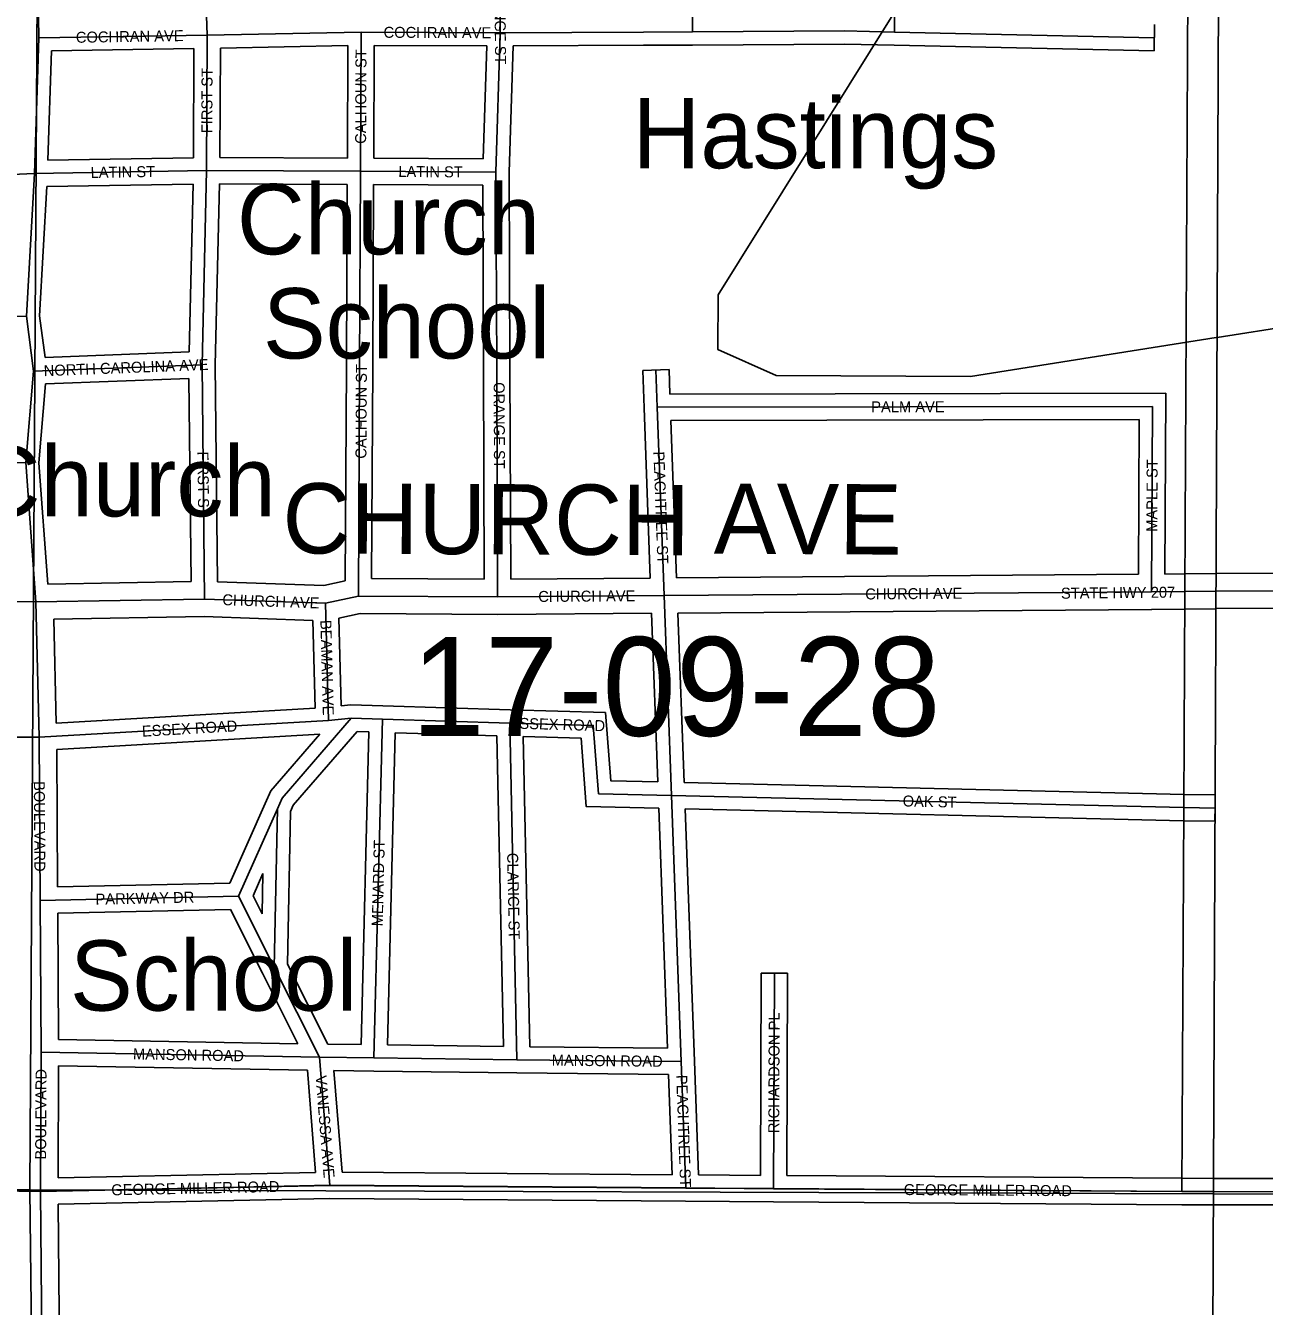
# Model space of a CAD drawing. Extents: x 418523 to 616617, y 1878279 to 2196743.
# Drawn here: x 494801 to 497620, y 1954823 to 1957739 of the extents above; entities that cross this region are included whole.
import ezdxf

# ---------------------------------------------------------------- set-up
doc = ezdxf.new("R2010")
doc.units = 0
for name, color, linetype in [('Level 1', 7, 'Continuous'), ('Level 2', 7, 'Continuous'), ('Level 22', 7, 'Continuous'), ('Level 23', 7, 'Continuous'), ('Level 28', 7, 'Continuous'), ('Level 31', 7, 'Continuous'), ('Level 32', 7, 'Continuous'), ('Level 34', 7, 'Continuous'), ('Level 44', 7, 'Continuous'), ('Level 57', 7, 'Continuous'), ('Level 63', 7, 'Continuous'), ('Level 7', 7, 'Continuous'), ('Level 8', 7, 'Continuous')]:
    doc.layers.add(name, color=color, linetype=linetype)

msp = doc.modelspace()

# ---------------------------------------------------------------- linework, layer by layer
at = {"layer": 'Level 1'}
for p, q in [((494842.153, 1960333.163), (494809.94, 1955087.849)), ((494809.94, 1955087.849), (489587.693, 1955086.288)), ((494809.94, 1955087.849), (494874.469, 1949774.808)), ((497503.83, 1955079.028), (494809.94, 1955087.849)), ((500077.56, 1955070.604), (497503.83, 1955079.028))]:
    msp.add_line(p, q, dxfattribs=at)
at = {"layer": 'Level 22'}
for p, q in [((495482.85, 1956423.768), (495557.843, 1956440.169)), ((495874.665, 1956438.423), (495557.843, 1956440.169)), ((495874.665, 1956438.423), (496253.728, 1956441.136)), ((496253.728, 1956441.136), (497362.983, 1956449.785)), ((497362.983, 1956449.785), (497438.86, 1956450.548)), ((494148.895, 1956430.348), (494824.127, 1956427.016)), ((495207.65, 1956433.336), (494824.127, 1956427.016)), ((494831.03, 1956118.601), (494824.127, 1956427.016)), ((495482.85, 1956423.768), (495207.65, 1956433.336)), ((494833.53, 1955746.929), (494831.03, 1956118.601)), ((494835.826, 1955401.441), (494833.53, 1955746.929)), ((494834.44, 1955084.699), (494835.826, 1955401.441))]:
    msp.add_line(p, q, dxfattribs=at)
for points in [[(497509.735, 1956451.334), (498093.802, 1956453.183), (498594.582, 1956559.406), (498750.081, 1956620.198)], [(497438.86, 1956450.548), (497509.658, 1956451.334), (497509.735, 1956451.334)], [(494935.568, 1953600.158), (494845.41, 1953892.572), (494834.44, 1955084.699)]]:
    msp.add_lwpolyline(points, dxfattribs=at)
at = {"layer": 'Level 23'}
for p, q in [((495177.235, 1956472.84), (494851.225, 1956467.468)), ((495479.216, 1956463.919), (495237.245, 1956472.331)), ((495479.216, 1956463.918), (495528.035, 1956474.595)), ((495844.52, 1956478.59), (495588.067, 1956480.003)), ((495904.521, 1956478.637), (496222.261, 1956480.912)), ((496282.286, 1956481.361), (497333.185, 1956489.553)), ((497393.189, 1956490.091), (497438.458, 1956490.546)), ((496285.214, 1956401.38), (497363.295, 1956409.785)), ((497363.386, 1956409.786), (497439.263, 1956410.549)), ((497439.305, 1956410.55), (497509.563, 1956411.33)), ((495207.286, 1956393.321), (494865.02, 1956387.682)), ((494870.318, 1956150.93), (494865.02, 1956387.683)), ((495453.876, 1956384.75), (495207.285, 1956393.321)), ((495513.77, 1956389.583), (495562.058, 1956400.143)), ((495874.952, 1956398.423), (495562.058, 1956400.143)), ((495874.952, 1956398.423), (496225.189, 1956400.93)), ((494873.324, 1955777.82), (494871.219, 1956090.879)), ((494875.634, 1955430.724), (494873.725, 1955717.813)), ((494874.576, 1955115.527), (494875.693, 1955370.711))]:
    msp.add_line(p, q, dxfattribs=at)
for points in [[(497509.907, 1956491.336), (498089.544, 1956493.171), (498583.072, 1956597.856), (498735.516, 1956657.453)], [(497509.563, 1956411.33), (497509.944, 1956411.334), (498098.06, 1956413.196), (498606.091, 1956520.956), (498764.647, 1956582.943)], [(497438.416, 1956490.546), (497509.372, 1956491.334), (497509.907, 1956491.336)], [(494970.103, 1953623.913), (494885.356, 1953898.779), (494874.71, 1955055.516)]]:
    msp.add_lwpolyline(points, dxfattribs=at)
at = {"layer": 'Level 31'}
for p, q in [((495213.895, 1957717.031), (495199.21, 1958134.214)), ((494830.385, 1957710.711), (494823.845, 1958102.402)), ((495880.887, 1957722.481), (495879.955, 1957799.946)), ((496317.39, 1957796.949), (496318.029, 1957724.578)), ((496778.001, 1957794.223), (496778.015, 1957724.036)), ((495213.895, 1957717.031), (495564.075, 1957723.863)), ((495562.694, 1957407.121), (495564.075, 1957723.863)), ((495880.887, 1957722.481), (495564.075, 1957723.863)), ((495870.935, 1957405.413), (495880.887, 1957722.481)), ((495880.887, 1957722.481), (496206.6, 1957723.972)), ((496206.6, 1957723.972), (496318.029, 1957724.578)), ((496318.029, 1957724.578), (496664.379, 1957726.711)), ((496664.379, 1957726.711), (496778.015, 1957724.036)), ((496778.015, 1957724.036), (497369.374, 1957711.296)), ((494820.462, 1957402.37), (494830.385, 1957710.711)), ((495213.895, 1957717.031), (494830.385, 1957710.711)), ((495212.547, 1957408.652), (495213.895, 1957717.031)), ((494145.101, 1957372.246), (494820.462, 1957402.37)), ((494802.214, 1957077.337), (494820.462, 1957402.37)), ((495212.547, 1957408.652), (494820.462, 1957402.37)), ((495202.045, 1956966.85), (495212.547, 1957408.652)), ((495562.694, 1957407.121), (495212.547, 1957408.652)), ((495560.756, 1956962.736), (495562.694, 1957407.121)), ((495870.935, 1957405.413), (495562.694, 1957407.121)), ((495872.802, 1956958.829), (495870.935, 1957405.413)), ((494126.92, 1957063.942), (494802.214, 1957077.337)), ((494818.49, 1956952.167), (494802.214, 1957077.337)), ((494818.49, 1956952.167), (495202.045, 1956966.85)), ((495207.65, 1956433.336), (495202.045, 1956966.85)), ((495557.843, 1956440.169), (495560.756, 1956962.736)), ((494800.752, 1956743.867), (494818.49, 1956952.167)), ((495874.665, 1956438.423), (495872.802, 1956958.829)), ((496235.007, 1956955.07), (496238.13, 1956869.96)), ((496238.13, 1956869.96), (497365.12, 1956871.985)), ((496238.13, 1956869.96), (496253.728, 1956441.136)), ((497365.12, 1956871.985), (497362.983, 1956449.785)), ((494133.744, 1956738.799), (494800.752, 1956743.867)), ((494824.127, 1956427.016), (494800.752, 1956743.867)), ((496253.728, 1956441.136), (496270.484, 1955986.125)), ((495489.94, 1956156.811), (495482.85, 1956423.768)), ((494831.03, 1956118.601), (495489.94, 1956156.811)), ((495541.71, 1956162.039), (495489.94, 1956156.811)), ((495541.71, 1956162.039), (495612.495, 1956159.911)), ((495612.495, 1956159.911), (495593.26, 1955388.308)), ((495612.495, 1956159.911), (495902.621, 1956151.009)), ((495902.621, 1956151.009), (495918.652, 1955384.343)), ((494164.045, 1956121.534), (494831.03, 1956118.601)), ((496270.484, 1955986.125), (497436.423, 1955958.526)), ((496270.484, 1955986.125), (496292.616, 1955380.17)), ((495285.015, 1955756.952), (495373.505, 1955955.851)), ((495373.505, 1955955.851), (495366.532, 1955594.767)), ((497436.423, 1955958.526), (497507.53, 1955957.129)), ((494833.53, 1955746.929), (495285.015, 1955756.952)), ((495285.015, 1955756.952), (495366.532, 1955594.767)), ((495366.532, 1955594.767), (495469.452, 1955389.94)), ((496502.8, 1955090.874), (496504.609, 1955581.444)), ((495469.452, 1955389.94), (494835.826, 1955401.441)), ((495492.943, 1955098.181), (495469.452, 1955389.94)), ((495469.452, 1955389.94), (495593.26, 1955388.308)), ((495593.26, 1955388.308), (495918.652, 1955384.343)), ((495918.652, 1955384.343), (496292.616, 1955380.17)), ((496292.616, 1955380.17), (496302.796, 1955092.107)), ((494834.44, 1955084.699), (495492.943, 1955098.181)), ((496302.796, 1955092.107), (495492.943, 1955098.181)), ((496502.8, 1955090.874), (496302.796, 1955092.107)), ((497432.022, 1955084.306), (496502.8, 1955090.874)), ((498740.975, 1955083.411), (497503.851, 1955083.997))]:
    msp.add_line(p, q, dxfattribs=at)
for points in [[(495373.505, 1955955.851), (495384.088, 1955980.171), (495541.71, 1956162.039)], [(495902.621, 1956151.009), (496092.442, 1956145.455), (496104.465, 1955990.12), (496270.484, 1955986.125)], [(493517.187, 1955074.501), (493992.548, 1955097.13), (494834.44, 1955084.699)], [(497503.851, 1955083.997), (497503.77, 1955083.997), (497432.022, 1955084.306)]]:
    msp.add_lwpolyline(points, dxfattribs=at)
at = {"layer": 'Level 32'}
for p, q in [((497370.02, 1957741.288), (497368.729, 1957681.301)), ((495243.767, 1957687.606), (495533.941, 1957693.268)), ((495532.825, 1957437.251), (495533.942, 1957693.268)), ((495592.825, 1957436.955), (495593.945, 1957693.731)), ((495849.935, 1957692.615), (495593.945, 1957693.731)), ((495841.868, 1957435.575), (495849.935, 1957692.615)), ((495900.94, 1957405.003), (495909.966, 1957692.612)), ((495909.966, 1957692.612), (496206.739, 1957693.971)), ((496206.765, 1957693.971), (496318.193, 1957694.578)), ((496318.215, 1957694.578), (496664.12, 1957696.706)), ((496664.12, 1957696.706), (496777.31, 1957694.043)), ((496777.37, 1957694.042), (497368.729, 1957681.301)), ((494851.46, 1957432.87), (494859.451, 1957681.184)), ((495183.761, 1957686.528), (494859.451, 1957681.184)), ((495182.676, 1957438.176), (495183.761, 1957686.528)), ((495242.679, 1957438.521), (495243.767, 1957687.607)), ((495182.676, 1957438.177), (494851.46, 1957432.87)), ((495532.825, 1957437.251), (495242.679, 1957438.521)), ((495841.868, 1957435.574), (495592.825, 1957436.955)), ((495902.802, 1956958.954), (495900.939, 1957405.003)), ((494832.324, 1957078.439), (494848.852, 1957372.82)), ((495181.814, 1957378.154), (494848.852, 1957372.82)), ((495172.725, 1956995.75), (495181.815, 1957378.154)), ((495232.05, 1956966.65), (495241.84, 1957378.521)), ((495532.564, 1957377.251), (495241.84, 1957378.522)), ((495530.757, 1956962.867), (495532.564, 1957377.251)), ((495590.757, 1956962.605), (495592.564, 1957376.954)), ((495841.06, 1957375.576), (495592.564, 1957376.953)), ((495842.802, 1956958.704), (495841.06, 1957375.576)), ((494844.71, 1956983.192), (494832.324, 1957078.439)), ((494844.71, 1956983.192), (495172.725, 1956995.75)), ((495237.245, 1956472.331), (495232.051, 1956966.651)), ((495528.035, 1956474.595), (495530.757, 1956962.904)), ((495588.067, 1956480.003), (495590.757, 1956962.568)), ((494846.134, 1956923.201), (495172.371, 1956935.691)), ((495177.234, 1956472.84), (495172.371, 1956935.691)), ((495844.52, 1956478.59), (495842.802, 1956958.721)), ((495904.521, 1956478.638), (495902.802, 1956958.936)), ((496264.988, 1956956.17), (496205.027, 1956953.97)), ((496205.027, 1956953.97), (496208.15, 1956868.859)), ((496264.988, 1956956.17), (496267.049, 1956900.011)), ((494830.848, 1956743.696), (494846.134, 1956923.201)), ((496267.049, 1956900.011), (497395.275, 1956902.039)), ((497395.275, 1956902.04), (497393.189, 1956490.091)), ((496208.149, 1956868.869), (496222.262, 1956480.913)), ((496269.24, 1956840.014), (497334.969, 1956841.93)), ((496269.24, 1956840.013), (496282.286, 1956481.361)), ((497334.969, 1956841.929), (497333.185, 1956489.553)), ((494851.226, 1956467.468), (494830.848, 1956743.696)), ((495459.179, 1956185.076), (495453.876, 1956384.75)), ((495519.073, 1956189.906), (495513.77, 1956389.583)), ((496225.188, 1956400.93), (496239.331, 1956016.882)), ((496285.214, 1956401.38), (496299.425, 1956015.448)), ((494870.318, 1956150.93), (495459.179, 1956185.076)), ((495540.65, 1956192.083), (495519.073, 1956189.905)), ((495540.65, 1956192.083), (495613.396, 1956189.897)), ((495613.415, 1956189.897), (495903.541, 1956180.996)), ((494871.219, 1956090.881), (495470.455, 1956125.629)), ((495555.05, 1956131.623), (495581.761, 1956130.82)), ((495581.761, 1956130.819), (495564.009, 1955418.696)), ((495641.735, 1956128.998), (495624.009, 1955417.936)), ((495641.735, 1956128.998), (495873.224, 1956121.895)), ((495873.224, 1956121.896), (495888.01, 1955414.72)), ((495933.275, 1956120.097), (495948.04, 1955414.017)), ((496299.425, 1956015.447), (497437.133, 1955988.518)), ((497437.012, 1955988.521), (497507.738, 1955987.131)), ((497508.12, 1955987.124), (497507.63, 1955962.251)), ((497507.738, 1955987.131), (497508.12, 1955987.124)), ((495265.336, 1955786.523), (495346.095, 1955968.046)), ((495403.386, 1955949.329), (495396.671, 1955601.606)), ((496241.535, 1955956.811), (496261.488, 1955410.519)), ((496301.628, 1955955.377), (497435.713, 1955928.534)), ((496301.628, 1955955.377), (496322.598, 1955381.265)), ((497507.63, 1955962.209), (497506.941, 1955927.133)), ((497507.63, 1955962.251), (497507.63, 1955962.245)), ((497507.63, 1955962.245), (497507.63, 1955962.242)), ((497507.63, 1955962.242), (497507.63, 1955962.241)), ((497507.63, 1955962.241), (497507.63, 1955962.239)), ((497507.63, 1955962.239), (497507.63, 1955962.227)), ((497507.63, 1955962.227), (497507.63, 1955962.209)), ((497435.834, 1955928.531), (497506.941, 1955927.133)), ((495318.2, 1955757.732), (495340.648, 1955808.19)), ((495340.648, 1955808.19), (495338.879, 1955716.59)), ((494873.325, 1955777.821), (495265.337, 1955786.523)), ((495318.2, 1955757.733), (495338.879, 1955716.591)), ((494873.725, 1955717.812), (495266.726, 1955726.537)), ((495266.727, 1955726.537), (495339.728, 1955581.294)), ((495396.67, 1955601.605), (495488.075, 1955419.696)), ((495339.726, 1955581.297), (495420.353, 1955420.836)), ((496472.912, 1955121.059), (496474.609, 1955581.554)), ((496474.609, 1955581.554), (496534.609, 1955581.332)), ((496532.911, 1955120.663), (496534.609, 1955581.332)), ((495420.353, 1955420.836), (494875.634, 1955430.724)), ((495488.075, 1955419.696), (495564.008, 1955418.696)), ((495624.01, 1955417.936), (495888.01, 1955414.719)), ((495948.04, 1955414.017), (496261.489, 1955410.519)), ((495441.731, 1955360.436), (494875.694, 1955370.711)), ((495460.484, 1955127.523), (495441.731, 1955360.436)), ((495520.642, 1955127.974), (495502, 1955359.507)), ((495502, 1955359.507), (495592.865, 1955358.31)), ((495592.895, 1955358.309), (495918.286, 1955354.345)), ((496322.599, 1955381.229), (496331.762, 1955121.929)), ((495918.317, 1955354.345), (496263.646, 1955350.49)), ((496263.647, 1955350.49), (496271.71, 1955122.341)), ((494874.576, 1955115.527), (495460.483, 1955127.523)), ((496271.71, 1955122.341), (495520.643, 1955127.974)), ((496472.912, 1955121.059), (496331.763, 1955121.929)), ((497432.234, 1955114.306), (496532.911, 1955120.663)), ((498740.99, 1955113.411), (497503.98, 1955113.998)), ((494874.711, 1955055.516), (495493.138, 1955068.177)), ((496302.572, 1955062.107), (495493.138, 1955068.178)), ((496502.616, 1955060.873), (496302.612, 1955062.106)), ((497431.81, 1955054.306), (496502.59, 1955060.873)), ((498740.961, 1955053.411), (497503.722, 1955053.996))]:
    msp.add_line(p, q, dxfattribs=at)
for points in [[(495903.498, 1956180.997), (496120.272, 1956174.654), (496132.285, 1956019.46), (496239.331, 1956016.882)], [(495346.095, 1955968.046), (495358.41, 1955996.351), (495470.455, 1956125.629)], [(495403.385, 1955949.329), (495409.765, 1955963.99), (495555.05, 1956131.622)], [(495933.275, 1956120.098), (496064.612, 1956116.256), (496076.647, 1955960.779), (496241.535, 1955956.811)], [(497503.98, 1955113.998), (497503.841, 1955113.998), (497432.151, 1955114.307)], [(497503.722, 1955053.996), (497503.698, 1955053.996), (497431.892, 1955054.306)]]:
    msp.add_lwpolyline(points, dxfattribs=at)
at = {"layer": 'Level 63'}
for points in [[(457652.636, 1924182.684), (497370.053, 1923990.389), (497565.655, 1969446.889), (457897.306, 1969639.697), (457652.636, 1924182.684)], [(497370.053, 1923990.389), (537087.279, 1923840.983), (537233.896, 1969297.112), (497565.655, 1969446.889), (497370.053, 1923990.389)]]:
    msp.add_lwpolyline(points, dxfattribs=at)
at = {"layer": 'Level 7'}
for p, q in [((497512.22, 1957028.746), (498746.857, 1957223.191)), ((497509.962, 1957028.391), (497512.22, 1957028.746))]:
    msp.add_line(p, q, dxfattribs=at)
msp.add_lwpolyline([(497509.962, 1957028.391), (496950.935, 1956939.702), (496509.117, 1956942.067), (496376.064, 1957001.136), (496376.711, 1957126.18), (496822.365, 1957840.721), (496998.544, 1958048.178), (497258.204, 1958280.216), (497384.103, 1958437.951), (497426.471, 1958562.775), (497445.533, 1959012.836), (497521.83, 1959262.276)], dxfattribs=at)
at = {"layer": 'Level 8'}
msp.add_lwpolyline([(493498.576, 1959054.451), (493702.58, 1959049.453), (493808.581, 1959050.455), (494828.599, 1959053.466), (495470.61, 1959016.473), (496061.62, 1959013.48), (496359.625, 1959000.482), (496501.628, 1958994.484), (496771.632, 1958984.486), (496828.633, 1959009.488), (497004.635, 1959034.491), (497375.641, 1959032.495), (497451.643, 1959031.496), (497438.692, 1956450.436), (497436.701, 1955958.425), (497431.718, 1955084.405), (496502.702, 1955090.394), (496302.699, 1955092.392), (495492.685, 1955098.383), (494834.675, 1955084.375), (493992.66, 1955097.366), (493517.653, 1955074.36), (492703.64, 1955079.351)], dxfattribs=at)

# ---------------------------------------------------------------- texts
at = {"layer": 'Level 2'}
msp.add_text('17-09-28', height=225, dxfattribs=at).set_placement((495678.508, 1956121.747))
at = {"layer": 'Level 28'}
for s, p in [('CHURCH', (495384.98, 1956537.411)), ('AVE', (496366.487, 1956536.447))]:
    msp.add_text(s, height=160, rotation=359.7166, dxfattribs=at).set_placement(p)
at = {"layer": 'Level 34'}
for s, height, rotation, p in [('ORANGE ST', 25, 270.688758, (495866.887, 1957847.041)), ('COCHRAN AVE', 25, 0.943406, (494915.114, 1957699.607)), ('COCHRAN AVE', 25, 359.749328, (495615.183, 1957711.142)), ('CALHOUN ST', 25, 89.749089, (495575.464, 1957469.533)), ('FIRST ST', 24.9992, 89.748542, (495225.417, 1957493.814)), ('LATIN ST', 24.9992, 0.917272, (494948.688, 1957391.925)), ('LATIN ST', 25, 359.681733, (495648.714, 1957394.145)), ('NORTH CAROLINA AVE', 25, 2.191725, (494842.206, 1956940.567)), ('CALHOUN ST', 25, 89.679492, (495576.166, 1956752.738)), ('ORANGE ST', 24.9992, 270.203972, (495865.831, 1956926.913)), ('PALM AVE', 25, 0.102311, (496725.11, 1956858.337)), ('FIRST ST', 25, 270.600864, (495191.625, 1956768.936)), ('PEACHTREE ST', 25, 272.082186, (496229.3, 1956768.878)), ('MAPLE ST', 25, 89.708842, (497376.172, 1956586.177)), ('CHURCH AVE', 25, 358.008183, (495248.024, 1956419.426)), ('CHURCH AVE', 25, 0.409497, (495967.437, 1956426.588)), ('CHURCH AVE', 25, 0.44605, (496711.604, 1956432.207)), ('STATE HWY 207', 25, 0.575772, (497157.107, 1956433.925)), ('BEAMAN AVE', 25, 271.520189, (495471.366, 1956385.358)), ('ESSEX ROAD', 24.9992, 3.318067, (495065.942, 1956119.704)), ('ESSEX ROAD', 25, 358.323306, (495901.772, 1956138.531)), ('BOULEVARD', 24.9992, 270.384208, (494819.204, 1956018.657)), ('OAK ST', 24.9992, 358.643417, (496796.483, 1955961.171)), ('MENARD ST', 24.9992, 88.570794, (495613.229, 1955687.848)), ('CLARICE ST', 25, 271.196781, (495896.303, 1955855.271)), ('PARKWAY DR', 24.9992, 1.271086, (494959.896, 1955737.233)), ('RICHARDSON PL', 25, 89.787697, (496515.762, 1955217.059)), ('MANSON ROAD', 25, 358.959403, (495044.712, 1955385.15)), ('MANSON ROAD', 25, 359.36, (495997.784, 1955370.961)), ('BOULEVARD', 25, 89.748017, (494847.253, 1955157.032)), ('VANESSA AVE', 25, 274.602108, (495460.321, 1955347.601)), ('PEACHTREE ST', 25, 272.022714, (496281.196, 1955349.486)), ('GEORGE MILLER ROAD', 25, 1.172233, (494995.791, 1955075.503)), ('GEORGE MILLER ROAD', 25, 359.594389, (496799.136, 1955076.281))]:
    msp.add_text(s, height=height, rotation=rotation, dxfattribs=at).set_placement(p)
at = {"layer": 'Level 44'}
msp.add_text('Hastings', height=160, dxfattribs=at).set_placement((496181.742, 1957414.141))
at = {"layer": 'Level 57'}
for s, p in [('Church', (495281.51, 1957218.108)), ('School', (495340.642, 1956981.061)), ('Church', (494679.898, 1956621.481)), ('School', (494901.583, 1955496.112))]:
    msp.add_text(s, height=160, dxfattribs=at).set_placement(p)

doc.saveas('drawing.dxf')
